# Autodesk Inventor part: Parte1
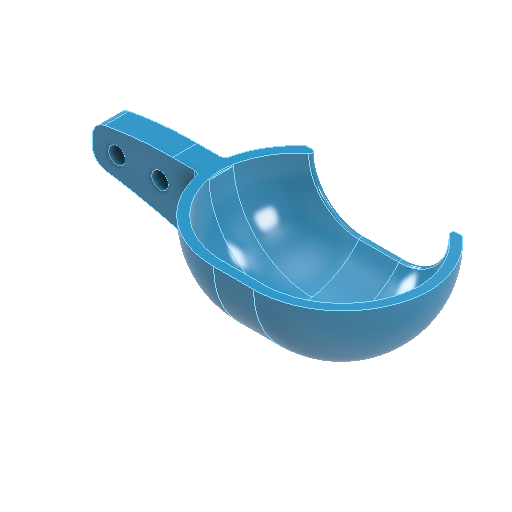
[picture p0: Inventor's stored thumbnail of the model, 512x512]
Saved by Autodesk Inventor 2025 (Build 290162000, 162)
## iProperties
Created: 2025-03
Part Number: Parte1
Material: Plastica ABS
Document SubType Name: Modeling
Designer: R5800u
Density: 1.06 g/cm^3
Appearance: Celeste scuro
Author: R5800u
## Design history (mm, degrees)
sketch "Schizzo1"
  geometry: L1 (-32.5, 25)-(32.5, 25); L2 (32.5, 25)-(32.5, -25); L3 (32.5, -25)-(-32.5, 25); L4 (-32.5, -25)-(32.5, 25); L5 (0, 0)-(0, 45.021); L6 (36.243, 0)-(-36.634, 0); L7 (35.5, 28)-(-35.5, 28); L8 (-35.5, 28)-(-35.5, -28); L9 (35.5, -28)-(35.5, 28); L10 (6.5, 25)-(-6.5, 25); L11 (35.483, 0)-(-35.483, 0); L12 (-32.5, -25)-(-32.5, -1); L13 (-32.5, 0)-(-32.5, 25); A1 r 26 centre (-6.5, -1) between (-6.5, 25) and (-32.481, 0); A2 r 26 centre (6.5, -1) between (32.481, 0) and (6.5, 25); A3 r 29 centre (6.5, -1) between (35.483, 0) and (6.5, 28); A4 r 29 centre (-6.5, -1) between (-6.5, 28) and (-35.483, 0); A5 r 29 centre (-6.5, -1) between (19.075, -14.673) and (19.332, -14.179); 8 further points
  constraints: 26 end point, 10 point on circle, 8 point on line, 5 centre point, 4 tangent, 3 parallel, 2 midpoint, 1 collinear, 1 horizontal, 1 symmetric about line, 1 vertical
  dimensions: "d0" = 65 distance of L1.start L1.end; "d1" = 50 distance of L4.start L1.start; "d7" = 3 radial gap between concentric circles of A2 A3; "d8" = 3 distance between parallel lines of L1 L7; "d15" = 13 distance of L10.end L10.start; "d16" = 26 radius of A2; "d17" = 26 radius of A1
revolve "Rivoluzione1" stored, may be unused: angle "d10" = 180 deg
sketch "Schizzo3"
  geometry: L1 (6.5, 28)-(60.739, 28); L2 (-35.697, 49)-(48.195, 49); L3 (13, 3)-(0, 3) reference; L4 (0, 53)-(13, 53) reference; L5 (13, 56)-(0, 56) reference; L6 (0, 0)-(13, 0) reference; A1 r 26 centre (13, 29) between (13, 3) and (38.981, 28) reference; A2 r 26 centre (0, 29) between (-25.981, 28) and (0, 3) reference; A3 r 26 centre (0, 27) between (0, 53) and (-25.981, 28) reference; A4 r 26 centre (13, 27) between (38.981, 28) and (13, 53) reference; A5 r 29 centre (13, 27) between (41.983, 28) and (13, 56) reference; A6 r 29 centre (0, 27) between (0, 56) and (-28.983, 28) reference; A7 r 29 centre (0, 29) between (-28.983, 28) and (0, 0) reference; A8 r 29 centre (13, 29) between (13, 0) and (41.983, 28) reference; 2 further points
  constraints: 4 end point, 2 horizontal
  dimensions: "d11" = 21 distance between parallel lines of L1 L2
extrude "Estrusione1" cut sketch "Schizzo3" extent not by distance; stored distance "d12" = 0; taper "d13" = 0 deg
fillet "Raccordo1" dims "d14" = 1
node "Piano di lavoro1"
node "Piano di lavoro2"
sketch "Schizzo5"
  geometry: L1 (0, 0)-(60, 0); L2 (0, -4)-(70, -4); L3 (70, -4)-(70, 4); L4 (70, 4)-(0, 4); L5 (0, 4)-(0, -4); L6 (-6.5, 28)-(-6.5, -21) reference; L7 (0, -4)-(-6.5, -4); L8 (-6.5, -4)-(-6.5, 4); L9 (-6.5, 4)-(0, 4); L10 (0, 4)-(0, -4); 3 further points
  constraints: 18 end point, 4 parallel, 3 horizontal, 2 midpoint, 2 perpendicular, 1 point on line, 1 other
  dimensions: "d23" = 8 distance of L3.end L2.end; "d35" = 70 distance from line of point (0, 0) L3
extrude "Estrusione2" join sketch "Schizzo5" stored distance "d24" = 10; taper "d25" = 0 deg
sketch "Schizzo 3D1"
sketch "Schizzo6"
  geometry: L1 (13, -24.678)-(0, -24.678) reference; L2 (38.515, 0)-(0, 0) reference; L3 (0, -24.678)-(0, 0) reference; 1 further point
  constraints: 1 other
  node "Linea chiusa proiettata2"
sketch "Schizzo7"
  geometry: L1 (38.515, -24.678)-(25.515, -24.678) reference; L2 (38.515, -24.678)-(38.515, 0) reference; L3 (38.515, 0)-(0, 0) reference; 1 further point
  constraints: 1 other
  node "Linea chiusa proiettata3"
loft "Loft1" dims "d26" = 0, "d27" = 90 deg, "d28" = 0, "d29" = 90 deg, "d30" = 0, "d31" = 90 deg
  node "Spigoli3"
  node "Spigoli4"
  node "Spigoli1"
sketch "Schizzo8"
  geometry: L1 (-16.971, 49)-(-18.894, 49) reference; L2 (-63.5, 32)-(-28.566, 32) reference; L3 (-63.5, 24)-(-63.5, 32) reference; L4 (-28.566, 24)-(-63.5, 24) reference; L5 (0, 0)-(13, 0) reference; L6 (31.894, 49)-(29.971, 49) reference; L7 (13, 3)-(0, 3) reference; L8 (13, 24)-(-25.515, 24) reference; L9 (13, 32)-(13, 24) reference; L10 (-25.515, 32)-(13, 32) reference; L11 (6.5, 28)-(6.5, 55.262); A1 r 26 centre (0, 27) between (-16.342, 47.222) and (-25.515, 32) reference; A2 r 29 centre (0, 27) between (-18.894, 49) and (-28.566, 32) reference; A3 r 29 centre (0, 29) between (-28.566, 24) and (0, 0) reference; A4 r 29 centre (13, 29) between (13, 0) and (41.983, 28) reference; A5 r 29 centre (13, 27) between (41.983, 28) and (31.894, 49) reference; A6 r 26 centre (13, 27) between (38.981, 28) and (29.342, 47.222) reference; A7 r 26 centre (13, 29) between (13, 3) and (38.981, 28) reference; A8 r 26 centre (0, 29) between (-25.515, 24) and (0, 3) reference; A9 r 26 centre (0, 27) between (-16.342, 47.222) and (-25.981, 28); A10 r 26 centre (0, 29) between (-25.981, 28) and (0, 3); 2 further points
  constraints: 4 point on circle, 3 symmetric about line, 2 centre point, 2 end point, 1 vertical, 4 other
extrude "Estrusione3" cut sketch "Schizzo8" distance "d32" = 0.5; taper "d33" = 0 deg
fillet "Raccordo2" dims "d34" = 2
sketch "Schizzo9"
  geometry: L1 (74.628, -29)-(0, -29) reference; L2 (0, -29)-(0, 0) reference; L3 (70, 0)-(70, -41.995); L4 (70, -8.5)-(60.091, -8.5); L5 (60.091, -8.5)-(0, -8.5); L6 (34.934, 0)-(0, 0) reference; C1 r 3 at (8, -8.5); C2 r 3 at (22, -8.5); A1 r 200 centre (-24.586, -212.483) between (55, -29) and (0, -14); A2 r 160 centre (38.843, -158.214) between (15, 0) and (0, -3); 2 further points
  constraints: 9 point on line, 6 end point, 4 centre point, 4 point on circle, 2 coincident, 1 perpendicular, 1 vertical
  dimensions: "d36" = 200 radius of A1; "d37" = 15 distance from line of L3 A1.start; "d38" = 14 vertical distance of L3.start A1.end; "d39" = 8.5 distance from line of L3.start L5; "d40" = 14 distance of point (8, -8.5) point (22, -8.5); "d41" = 8 horizontal distance of L2.end point (8, -8.5); "d42" = 6 diameter of C1; "d43" = 6 diameter of C2; "d49" = 160 radius of A2; "d50" = 15 distance from line of L2 A2.start; "d51" = 3 distance of L2.end A2.end
extrude "Estrusione4" cut sketch "Schizzo9" extent not by distance; stored distance "d44" = 0; taper "d45" = 0 deg
fillet "Raccordo4" dims "d47" = 50
node "Piano di lavoro3"
fillet "Raccordo5" dims "d52" = 5
fillet "Raccordo6" dims "d53" = 120
hole "Foro1" sketch "Schizzo9" diameter "d54" = 5.3; stored, may be unused: countersink angle "d58" = 90 deg, drill point angle "d60" = 118 deg; dims "d55" = 6, "d56" = 10.4, "d57" = 2, "d59" = 8
fillet "Raccordo7" dims "d61" = 2
node "Solido1"
node "Linea chiusa proiettata1"
node "Linea chiusa proiettata4"
other parameters: "d2" = 52, "d18" = -28, "d21" = -29, "d48" = -7
